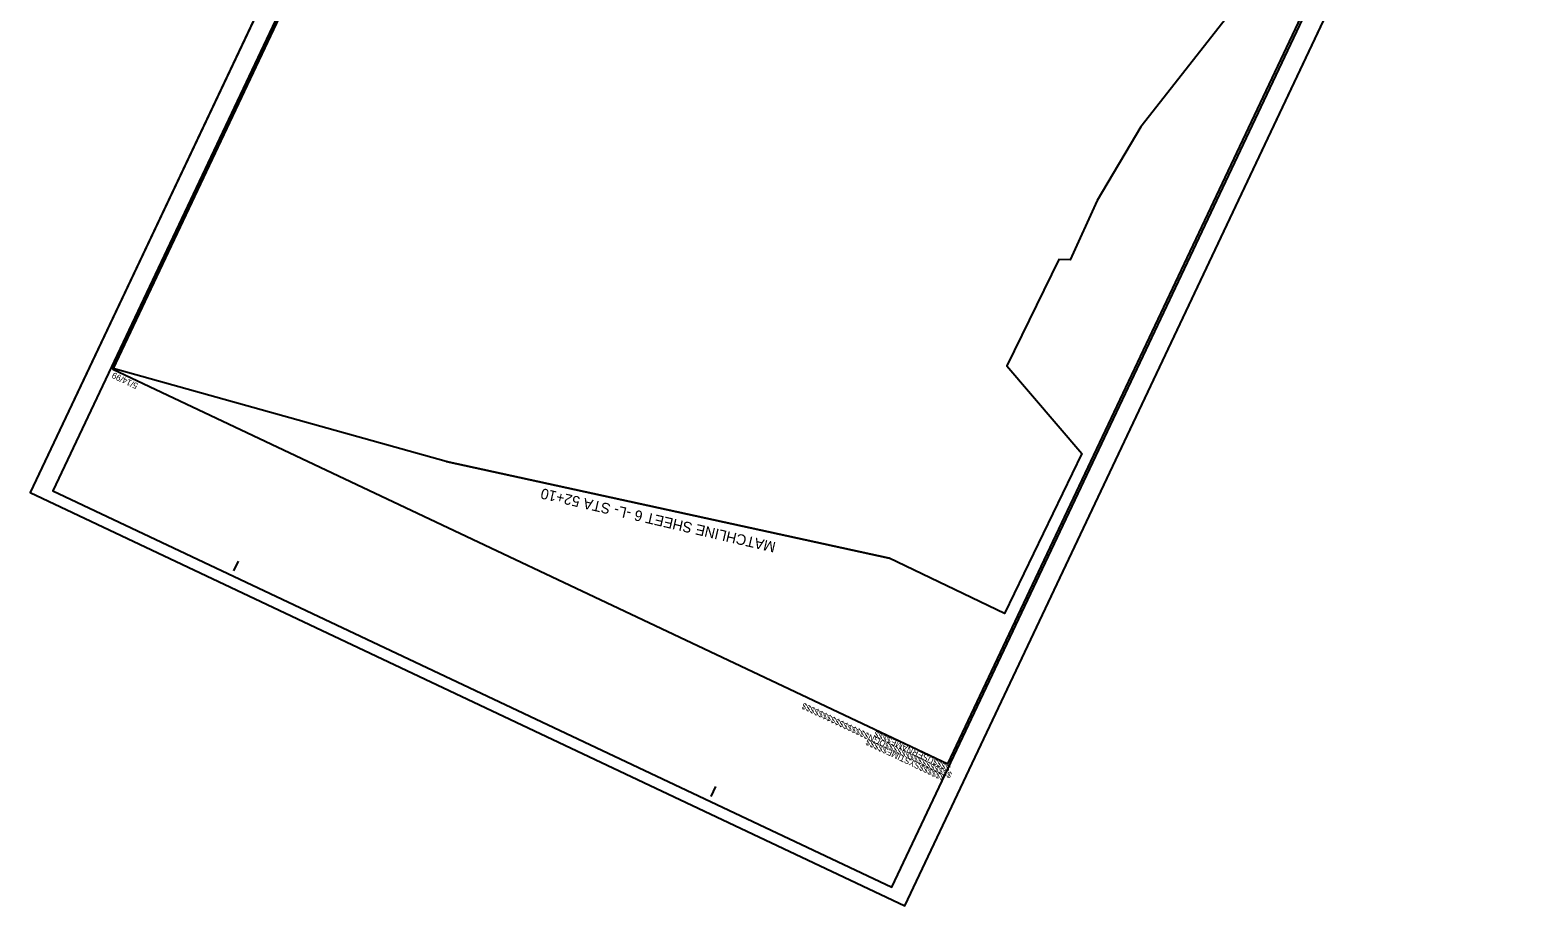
# Model space of a CAD drawing. Extents: x 556536 to 558250, y 505355 to 507347.
# Drawn here: x 556536 to 558250, y 505355 to 506351 of the extents above; entities that cross this region are included whole.
import ezdxf

# ---------------------------------------------------------------- set-up
doc = ezdxf.new("R2010")
doc.units = 0
for name, color, linetype in [('Prop Drainage Structure Box Number Symbol CELL', 7, 'Continuous'), ('Prop Drainage Structure Catch Basin Grate 840 03G CELL', 7, 'Continuous'), ('Prop Earthen Structure Base Ditch Lateral Detail Label', 7, 'Continuous'), ('Prop Earthen Structure Berm Ditch Detail CELL', 7, 'Continuous'), ('Prop Earthen Structure Berm Ditch Detail Label', 7, 'Continuous'), ('Prop Earthen Structure V Ditch Lateral Detail CELL', 7, 'Continuous'), ('Prop Erosion Rip Rap Class B', 7, 'Continuous')]:
    doc.layers.add(name, color=color, linetype=linetype)

msp = doc.modelspace()

# ---------------------------------------------------------------- linework, layer by layer
at = {"layer": 'Prop Drainage Structure Box Number Symbol CELL'}
msp.add_lwpolyline([(557273.7, 507333.5), (556561.6, 505826.8), (557515.5, 505375.9), (558227.7, 506882.6)], close=True, dxfattribs=at)
at = {"layer": 'Prop Drainage Structure Catch Basin Grate 840 03G CELL'}
msp.add_lwpolyline([(557798.5, 506240.9), (557748.8, 506157), (557718.1, 506089.7), (557705.4, 506089.8), (557646.2, 505968.9), (557731.5, 505869.1), (557643.4, 505687.1), (557512.4, 505750.3), (557008.7, 505860.1), (556630.1, 505965.9), (557185.2, 507140.2), (557323.6, 507073.6), (557372.9, 507179), (557443.2, 507138.3), (557473.7, 506971.8), (557393.3, 506960), (557425.5, 506933.6), (557889.7, 506539.4), (557955, 506511.1), (557971.1, 506460.7)], close=True, dxfattribs=at)
at = {"layer": 'Prop Earthen Structure Base Ditch Lateral Detail Label'}
msp.add_lwpolyline([(557255.4, 507347.2), (556535.8, 505824.7), (557530.3, 505354.6), (558249.9, 506877.1)], close=True, dxfattribs=at)
at = {"layer": 'Prop Earthen Structure Berm Ditch Detail Label'}
for p, q in [((557255.4, 507347.2), (556535.8, 505824.7)), ((557530.3, 505354.6), (558249.9, 506877.1)), ((556535.8, 505824.7), (557530.3, 505354.6))]:
    msp.add_line(p, q, dxfattribs=at)
at = {"layer": 'Prop Earthen Structure V Ditch Lateral Detail CELL'}
msp.add_line((557008.7, 505860.1), (557512.4, 505750.3), dxfattribs=at)
at = {"layer": 'Prop Erosion Rip Rap Class B'}
for p, q in [((556630.1, 505965.9), (556630.1, 505965.9)), ((556767.4, 505735.6), (556772.8, 505746.9)), ((557309.9, 505479.2), (557315.2, 505490.5))]:
    msp.add_line(p, q, dxfattribs=at)
msp.add_lwpolyline([(557270.7, 507321.1), (556629.7, 505965), (557579, 505516.3), (558220, 506872.4)], close=True, dxfattribs=at)

# ---------------------------------------------------------------- texts
at = {"layer": 'Prop Earthen Structure Berm Ditch Detail CELL'}
msp.add_text('MATCHLINE SHEET 6 -L- STA 52+10', height=12, rotation=166.9353, dxfattribs=at).set_placement((557384.2, 505768.1))
at = {"layer": 'Prop Erosion Rip Rap Class B'}
for s, p in [('5/14/99', (556659, 505948.6)), ('$$$$$$$$$$$$$$$$DGN$$$$$$$$$$$$$$$$', (557584.6, 505505.7)), ('$$$$USERNAME$$$$', (557582.9, 505513.5)), ('$$$$$$SYSTIME$$$$$', (557576.8, 505502.7))]:
    msp.add_text(s, height=7, rotation=154.7021, dxfattribs=at).set_placement(p)

doc.saveas('drawing.dxf')
